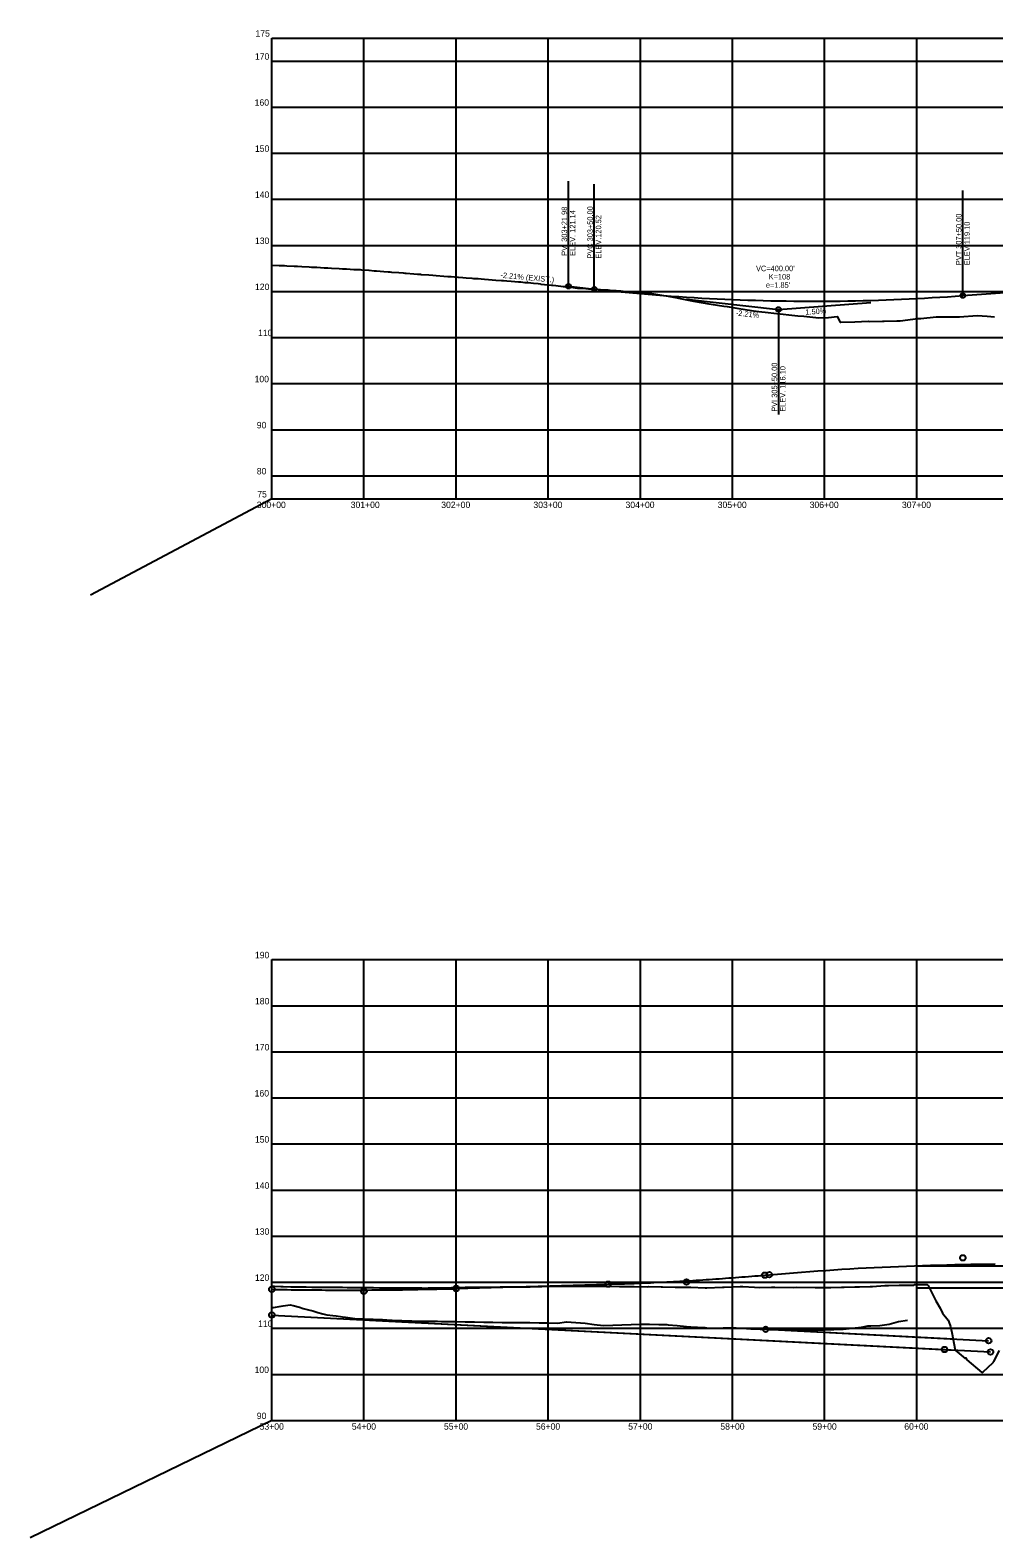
# Model space of a CAD drawing. Extents: x 1191541 to 1200065, y 1475807 to 1480451.
# Drawn here: x 1193644 to 1194690, y 1478815 to 1480451 of the extents above; entities that cross this region are included whole.
import ezdxf

# ---------------------------------------------------------------- set-up
doc = ezdxf.new("R2010")
doc.units = 0
for name, color, linetype in [('R_Exist Surface', 7, 'Continuous'), ('R_Grid', 7, 'Continuous'), ('R_No Plot', 7, 'Continuous'), ('R_Proposed Const Limits_Fill', 7, 'Continuous'), ('R_Proposed Const Limits_Hand', 7, 'Continuous'), ('R_Vert Alg', 7, 'Continuous'), ('R_Vert Alg Annot', 7, 'Continuous'), ('R_Water', 7, 'Continuous')]:
    doc.layers.add(name, color=color, linetype=linetype)

msp = doc.modelspace()

# ---------------------------------------------------------------- linework, layer by layer
at = {"layer": 'R_Exist Surface'}
msp.add_line((1193906.3, 1479942.5), (1193709.7, 1479838), dxfattribs=at)
for points in [[(1193906.3, 1480196.2), (1193906.5, 1480196.1), (1193914.4, 1480195.8), (1193918, 1480195.6), (1193920.1, 1480195.5), (1193922.5, 1480195.4), (1193930.7, 1480195), (1193931.8, 1480194.9), (1193934.2, 1480194.8), (1193938.8, 1480194.6), (1193946.9, 1480194.2), (1193949.4, 1480194), (1193951.7, 1480193.9), (1193955, 1480193.7), (1193963.1, 1480193.3), (1193967, 1480193.1), (1193971.2, 1480192.9), (1193979.3, 1480192.4), (1193983.2, 1480192.2), (1193984.5, 1480192.2), (1193987.4, 1480192), (1193995.5, 1480191.5), (1194001.7, 1480191.2), (1194002.1, 1480191.2), (1194003.6, 1480191.1), (1194011.7, 1480190.5), (1194011.8, 1480190.5), (1194017.5, 1480190), (1194017.7, 1480190), (1194019.9, 1480189.8), (1194028, 1480189.2), (1194032.5, 1480188.9), (1194033.4, 1480188.8), (1194034.3, 1480188.7), (1194036.1, 1480188.6), (1194044.2, 1480187.9), (1194049, 1480187.6), (1194050.8, 1480187.4), (1194052.3, 1480187.3), (1194060.4, 1480186.6), (1194064.6, 1480186.3), (1194067.7, 1480186.1), (1194068.5, 1480186), (1194076.6, 1480185.4), (1194080.9, 1480185.1), (1194084.7, 1480184.8), (1194092.9, 1480184.2), (1194092.9, 1480184.2), (1194097.2, 1480183.9), (1194101, 1480183.6), (1194108.3, 1480183), (1194109.1, 1480183), (1194113.6, 1480182.6), (1194117.2, 1480182.3), (1194123.5, 1480181.8), (1194125.3, 1480181.7), (1194130.1, 1480181.4), (1194133.4, 1480181.1), (1194137.2, 1480180.9), (1194141.5, 1480180.5), (1194149.4, 1480179.9), (1194149.6, 1480179.9), (1194155.7, 1480179.5), (1194157.7, 1480179.3), (1194161.2, 1480179.1), (1194165.9, 1480178.7), (1194174, 1480178), (1194176.7, 1480177.8), (1194181, 1480177.4), (1194182.1, 1480177.3), (1194184.7, 1480177.1), (1194190.2, 1480176.5), (1194195.3, 1480176), (1194197.9, 1480175.7), (1194198.3, 1480175.6), (1194206.4, 1480174.8), (1194209.8, 1480174.4), (1194211.4, 1480174.2), (1194214.5, 1480173.9), (1194222.6, 1480173), (1194224.7, 1480172.8), (1194225, 1480172.7), (1194228.3, 1480172.4), (1194230.7, 1480172.1), (1194237.9, 1480171.2), (1194238.8, 1480171.2), (1194239.6, 1480171.1), (1194247, 1480170.7), (1194250.1, 1480170.5), (1194253.2, 1480170.3), (1194255.1, 1480170.2), (1194261.9, 1480169.8), (1194263.2, 1480169.7), (1194266.7, 1480169.4), (1194271.3, 1480169.1), (1194273.5, 1480169), (1194279.4, 1480168.6), (1194280.1, 1480168.5), (1194285, 1480168.2), (1194287.5, 1480168), (1194293.6, 1480167.6), (1194295.6, 1480167.5), (1194297.2, 1480167.4), (1194303.7, 1480166.8), (1194311.6, 1480166.2), (1194312.4, 1480166.1), (1194316.6, 1480165.8), (1194325.1, 1480164.3), (1194329.6, 1480163.5), (1194336.4, 1480162.3), (1194346.1, 1480160.5), (1194347.6, 1480160.2), (1194347.8, 1480160.1), (1194364.1, 1480156.9), (1194366, 1480156.5), (1194380.7, 1480154.2), (1194383.2, 1480153.8), (1194397, 1480151.7), (1194400.4, 1480151.1), (1194413.2, 1480149.1), (1194417.7, 1480148.4), (1194429.2, 1480146.6), (1194434.9, 1480145.6), (1194445, 1480144.5), (1194451.2, 1480144), (1194461.1, 1480142.9), (1194467.5, 1480142.3), (1194477.2, 1480141.2), (1194483.7, 1480140.7), (1194493.3, 1480139.6), (1194500, 1480139), (1194510.4, 1480139.4), (1194519.8, 1480140.5), (1194523.3, 1480134.3), (1194523.9, 1480134.3), (1194539.2, 1480134.7), (1194553.5, 1480135.1), (1194555, 1480135), (1194569, 1480135.3), (1194570.8, 1480135.2), (1194584.6, 1480135.5), (1194586.4, 1480135.5), (1194588.2, 1480135.5), (1194607.5, 1480138), (1194610.6, 1480138), (1194627.5, 1480140), (1194631.6, 1480140.1), (1194649.8, 1480139.9), (1194651.5, 1480140.1), (1194652.5, 1480140.1), (1194671.9, 1480141.6), (1194682.6, 1480140.7), (1194686.5, 1480140.3), (1194690.8, 1480139.9)], [(1193906.3, 1479088.2), (1193908, 1479088.1), (1193909.4, 1479088.1), (1193916.2, 1479087.9), (1193918.8, 1479087.9), (1193926.8, 1479087.6), (1193929.5, 1479087.5), (1193933.7, 1479087.4), (1193940.2, 1479087.4), (1193943.6, 1479087.4), (1193949.9, 1479087.3), (1193951, 1479087.3), (1193959.7, 1479087.2), (1193961.7, 1479087.2), (1193966, 1479087.2), (1193972.4, 1479087.1), (1193976, 1479087.1), (1193982.1, 1479087), (1193983.1, 1479087), (1193988, 1479086.9), (1193993.9, 1479086.8), (1193998.2, 1479086.8), (1194004.6, 1479086.7), (1194004.8, 1479086.7), (1194015.3, 1479086.7), (1194016.8, 1479086.7), (1194023.2, 1479086.6), (1194026.1, 1479086.6), (1194035.3, 1479086.6), (1194036.8, 1479086.6), (1194041.3, 1479086.5), (1194047.5, 1479086.5), (1194053.9, 1479086.4), (1194058.2, 1479086.3), (1194059.3, 1479086.3), (1194069, 1479086.3), (1194072.5, 1479086.2), (1194076.1, 1479086.3), (1194079.7, 1479086.3), (1194087, 1479086.5), (1194090.4, 1479086.5), (1194090.5, 1479086.5), (1194101.2, 1479086.7), (1194101.6, 1479086.8), (1194104.7, 1479086.8), (1194116.2, 1479087), (1194118.9, 1479087), (1194130.8, 1479087.3), (1194134.1, 1479087.3), (1194151.9, 1479087.3), (1194154.3, 1479087.4), (1194172.9, 1479087.4), (1194174, 1479087.4), (1194185.7, 1479087.6), (1194186.7, 1479087.6), (1194198.5, 1479087.9), (1194199.5, 1479087.9), (1194211.3, 1479088.1), (1194223.2, 1479088.3), (1194224.1, 1479088.3), (1194238, 1479088.2), (1194239, 1479088.2), (1194252.9, 1479088.2), (1194253.8, 1479088.2), (1194254.8, 1479088.1), (1194268.7, 1479088.1), (1194269.5, 1479088.1), (1194283.5, 1479088), (1194284.3, 1479088), (1194298.6, 1479087.8), (1194299.7, 1479087.8), (1194313.7, 1479087.6), (1194315.1, 1479087.7), (1194328.9, 1479087.5), (1194330.5, 1479087.5), (1194344, 1479087.3), (1194359.2, 1479087), (1194361.1, 1479087), (1194376.6, 1479086.6), (1194378.3, 1479086.6), (1194395.4, 1479087.3), (1194397.1, 1479087.3), (1194414.7, 1479087.9), (1194415.7, 1479087.9), (1194417.6, 1479087.9), (1194430.3, 1479087.1), (1194435.6, 1479086.8), (1194448.7, 1479087.2), (1194452.3, 1479087.2), (1194472.7, 1479086.9), (1194475.3, 1479087), (1194496, 1479086.7), (1194498.5, 1479086.7), (1194500.8, 1479086.7), (1194513, 1479086.9), (1194524.7, 1479087.2), (1194527.6, 1479087.2), (1194539.1, 1479087.4), (1194541.7, 1479087.5), (1194544.2, 1479087.6), (1194555.8, 1479087.8), (1194558.4, 1479087.9), (1194571.7, 1479088.8), (1194572.3, 1479088.8), (1194575.5, 1479089.1), (1194587, 1479089.2), (1194588.6, 1479089.2), (1194602.5, 1479089.2), (1194603.1, 1479089.3), (1194604.2, 1479090.2), (1194617.5, 1479090.2), (1194618.6, 1479088.9), (1194625.2, 1479076), (1194627, 1479072.3), (1194631.5, 1479064.2), (1194634.2, 1479059), (1194640.2, 1479051.4), (1194640.9, 1479049.6), (1194643, 1479044.4), (1194644.2, 1479037.9), (1194647.8, 1479018.9), (1194658.8, 1479009.7), (1194659.7, 1479010.3), (1194660.5, 1479008.4), (1194676.8, 1478994.6), (1194678.4, 1478995.4), (1194688.7, 1479005.1), (1194689.5, 1479005.9), (1194689.6, 1479006), (1194689.9, 1479006.5), (1194696, 1479018.5)]]:
    msp.add_lwpolyline(points, dxfattribs=at)
at = {"layer": 'R_Grid'}
for p, q in [((1193906.3, 1480442.5), (1196406.3, 1480442.5)), ((1194006.3, 1479942.5), (1194006.3, 1480442.5)), ((1194106.3, 1479942.5), (1194106.3, 1480442.5)), ((1194206.3, 1479942.5), (1194206.3, 1480442.5)), ((1194306.3, 1479942.5), (1194306.3, 1480442.5)), ((1194406.3, 1479942.5), (1194406.3, 1480442.5)), ((1194506.3, 1479942.5), (1194506.3, 1480442.5)), ((1194606.3, 1479942.5), (1194606.3, 1480442.5)), ((1193906.3, 1480417.5), (1196406.3, 1480417.5)), ((1193906.3, 1480367.5), (1196406.3, 1480367.5)), ((1193906.3, 1480317.5), (1196406.3, 1480317.5)), ((1193906.3, 1480267.5), (1196406.3, 1480267.5)), ((1193906.3, 1480217.5), (1196406.3, 1480217.5)), ((1193906.3, 1480167.5), (1196406.3, 1480167.5)), ((1193906.3, 1480117.5), (1196406.3, 1480117.5)), ((1193906.3, 1480067.5), (1196406.3, 1480067.5)), ((1193906.3, 1480017.5), (1196406.3, 1480017.5)), ((1193906.3, 1479967.5), (1196406.3, 1479967.5)), ((1193906.3, 1479442.5), (1195406.3, 1479442.5)), ((1193906.3, 1479442.5), (1195406.3, 1479442.5)), ((1194006.3, 1478942.5), (1194006.3, 1479442.5)), ((1194106.3, 1478942.5), (1194106.3, 1479442.5)), ((1194206.3, 1478942.5), (1194206.3, 1479442.5)), ((1194306.3, 1478942.5), (1194306.3, 1479442.5)), ((1194406.3, 1478942.5), (1194406.3, 1479442.5)), ((1194506.3, 1478942.5), (1194506.3, 1479442.5)), ((1194606.3, 1478942.5), (1194606.3, 1479442.5)), ((1193906.3, 1479392.5), (1195406.3, 1479392.5)), ((1193906.3, 1479342.5), (1195406.3, 1479342.5)), ((1193906.3, 1479292.5), (1195406.3, 1479292.5)), ((1193906.3, 1479242.5), (1195406.3, 1479242.5)), ((1193906.3, 1479192.5), (1195406.3, 1479192.5)), ((1193906.3, 1479142.5), (1195406.3, 1479142.5)), ((1193906.3, 1479092.5), (1195406.3, 1479092.5)), ((1193906.3, 1479042.5), (1195406.3, 1479042.5)), ((1193906.3, 1478992.5), (1195406.3, 1478992.5))]:
    msp.add_line(p, q, dxfattribs=at)
at = {"layer": 'R_No Plot'}
for p, q in [((1194606.3, 1479110.3), (1194786.3, 1479110.3)), ((1194606.3, 1478942.5), (1194606.3, 1479110.3)), ((1194606.3, 1479086.5), (1194786.3, 1479086.5)), ((1193906.3, 1479056.9), (1194647.8, 1479018.9)), ((1194443.2, 1479041.4), (1194645.8, 1479031)), ((1193906.3, 1478942.5), (1193644, 1478815.2))]:
    msp.add_line(p, q, dxfattribs=at)
at = {"layer": 'R_Proposed Const Limits_Fill'}
msp.add_lwpolyline([(1193906.3, 1479065.2), (1193908, 1479065.1), (1193916.3, 1479066.5), (1193918.8, 1479067), (1193926.3, 1479067.9), (1193929.5, 1479067.3), (1193936.3, 1479065.3), (1193940.2, 1479064.1), (1193946.3, 1479062.7), (1193951, 1479061.3), (1193956.3, 1479059.7), (1193961.7, 1479058.1), (1193966.2, 1479057.3), (1193966.3, 1479057.3), (1193972.4, 1479056.5), (1193976.3, 1479055.9), (1193983.1, 1479055), (1193986.3, 1479054.5), (1193993.9, 1479053.5), (1193996.3, 1479053.3), (1194004.6, 1479052.9), (1194006.3, 1479052.8), (1194015.3, 1479052.4), (1194016.3, 1479052.4), (1194026.1, 1479051.9), (1194026.3, 1479051.9), (1194036.3, 1479051.4), (1194036.8, 1479051.4), (1194046.3, 1479051), (1194047.5, 1479051), (1194056.3, 1479050.6), (1194058.2, 1479050.6), (1194066.3, 1479050.4), (1194069, 1479050.4), (1194076.3, 1479050.2), (1194079.7, 1479050.2), (1194086.3, 1479050.1), (1194090.4, 1479050), (1194096.3, 1479049.9), (1194101.2, 1479049.9), (1194106.3, 1479049.8), (1194116.3, 1479049.6), (1194126.3, 1479049.5), (1194136.3, 1479049.3), (1194146.3, 1479049.2), (1194156.3, 1479048.9), (1194166.3, 1479048.7), (1194176.3, 1479048.7), (1194186.3, 1479048.7), (1194196.3, 1479048.6), (1194206.3, 1479048.6), (1194216.3, 1479048.2), (1194226.3, 1479049.6), (1194236.3, 1479048.8), (1194246.3, 1479048), (1194256.3, 1479046.6), (1194266.3, 1479045.6), (1194276.3, 1479046), (1194286.3, 1479046.4), (1194296.3, 1479046.8), (1194306.3, 1479047.1), (1194309.8, 1479047), (1194316.3, 1479046.9), (1194326.3, 1479046.7), (1194335.2, 1479046.5), (1194336.3, 1479046.4), (1194346.3, 1479045.4), (1194356.3, 1479044.4), (1194366.3, 1479043.9), (1194368.2, 1479043.7), (1194376.3, 1479043.3), (1194378.2, 1479043.1), (1194386.3, 1479042.8), (1194396.3, 1479043.1), (1194406.3, 1479043.3), (1194410.2, 1479043.1), (1194416.3, 1479042.6), (1194426.3, 1479041.9), (1194436.3, 1479041.6), (1194443.2, 1479041.4), (1194446.3, 1479041.3), (1194453.2, 1479041.3), (1194456.3, 1479041.4), (1194466.3, 1479041.2), (1194476.3, 1479040.9), (1194486.3, 1479040.7), (1194496.3, 1479040.7), (1194506.2, 1479040.9), (1194506.3, 1479040.9), (1194516.3, 1479041.2), (1194526.3, 1479041.6), (1194536.3, 1479042.7), (1194546.3, 1479043.7), (1194553.2, 1479045.1), (1194556.3, 1479045.2), (1194566.3, 1479045.7), (1194576.3, 1479047), (1194586.3, 1479049.9), (1194596.3, 1479051.4)], dxfattribs=at)
at = {"layer": 'R_Vert Alg'}
for p, q in [((1194656.3, 1480163), (1194997.1, 1480188.5)), ((1194228.3, 1480173.2), (1194256.3, 1480170.1)), ((1194356.3, 1480159.1), (1194456.3, 1480148)), ((1194456.3, 1480148), (1194556.3, 1480155.5)), ((1194106.3, 1479085.7), (1194271.3, 1479090.4)), ((1194441.3, 1479100.2), (1194446.3, 1479100.7)), ((1193906.3, 1479056.9), (1194686.3, 1479016.9)), ((1193906.3, 1479056.9), (1194636.3, 1479019.5)), ((1194442.3, 1479041.4), (1194684.3, 1479029))]:
    msp.add_line(p, q, dxfattribs=at)
for points in [[(1194256.3, 1480170.1), (1194264.7, 1480169.2), (1194273, 1480168.4), (1194281.3, 1480167.5), (1194289.7, 1480166.7), (1194298, 1480165.9), (1194306.3, 1480165.2), (1194314.7, 1480164.5), (1194323, 1480163.8), (1194331.3, 1480163.1), (1194339.7, 1480162.5), (1194348, 1480161.9), (1194356.3, 1480161.4), (1194364.7, 1480160.9), (1194373, 1480160.4), (1194381.3, 1480159.9), (1194389.7, 1480159.5), (1194398, 1480159.1), (1194406.3, 1480158.8), (1194414.7, 1480158.4), (1194423, 1480158.1), (1194431.3, 1480157.9), (1194439.7, 1480157.7), (1194448, 1480157.5), (1194464.7, 1480157.2), (1194473, 1480157.1), (1194481.3, 1480157), (1194489.7, 1480157), (1194498, 1480157), (1194506.3, 1480157), (1194514.7, 1480157), (1194523, 1480157.1), (1194531.3, 1480157.3), (1194539.7, 1480157.4), (1194548, 1480157.6), (1194556.3, 1480157.8), (1194564.7, 1480158.1), (1194573, 1480158.4), (1194581.3, 1480158.7), (1194589.7, 1480159), (1194598, 1480159.4), (1194606.3, 1480159.8), (1194614.7, 1480160.3), (1194623, 1480160.8), (1194631.3, 1480161.3), (1194639.7, 1480161.8), (1194648, 1480162.4), (1194656.3, 1480163)], [(1194446.3, 1479100.7), (1194455.1, 1479101.4), (1194463.8, 1479102.1), (1194472.6, 1479102.8), (1194481.3, 1479103.5), (1194490.1, 1479104.2), (1194498.8, 1479104.8), (1194507.6, 1479105.4), (1194516.3, 1479106), (1194525.1, 1479106.5), (1194533.8, 1479107.1), (1194542.6, 1479107.6), (1194551.3, 1479108), (1194560.1, 1479108.5), (1194568.8, 1479108.9), (1194577.6, 1479109.3), (1194586.3, 1479109.7), (1194595.1, 1479110), (1194603.8, 1479110.4), (1194612.6, 1479110.7), (1194621.3, 1479111), (1194630.1, 1479111.2), (1194638.8, 1479111.4), (1194647.6, 1479111.6), (1194665.1, 1479112), (1194673.8, 1479112.1), (1194682.6, 1479112.2), (1194691.3, 1479112.3)], [(1194271.3, 1479090.4), (1194274.9, 1479090.5), (1194278.4, 1479090.6), (1194281.9, 1479090.7), (1194285.5, 1479090.8), (1194289, 1479090.9), (1194292.6, 1479091), (1194296.1, 1479091.2), (1194299.7, 1479091.3), (1194303.2, 1479091.4), (1194306.7, 1479091.6), (1194310.3, 1479091.7), (1194313.8, 1479091.9), (1194317.4, 1479092), (1194320.9, 1479092.2), (1194324.4, 1479092.4), (1194328, 1479092.5), (1194331.5, 1479092.7), (1194335.1, 1479092.9), (1194338.6, 1479093.1), (1194342.2, 1479093.2), (1194345.7, 1479093.4), (1194349.2, 1479093.6), (1194352.8, 1479093.8), (1194359.9, 1479094.2), (1194363.4, 1479094.5), (1194366.9, 1479094.7), (1194370.5, 1479094.9), (1194374, 1479095.1), (1194377.6, 1479095.3), (1194381.1, 1479095.6), (1194384.7, 1479095.8), (1194388.2, 1479096.1), (1194391.7, 1479096.3), (1194395.3, 1479096.6), (1194398.8, 1479096.8), (1194402.4, 1479097.1), (1194405.9, 1479097.3), (1194409.4, 1479097.6), (1194413, 1479097.9), (1194416.5, 1479098.2), (1194420.1, 1479098.4), (1194423.6, 1479098.7), (1194427.2, 1479099), (1194430.7, 1479099.3), (1194434.2, 1479099.6), (1194437.8, 1479099.9), (1194441.3, 1479100.2)], [(1193906.3, 1479084.8), (1193910.5, 1479084.7), (1193914.7, 1479084.6), (1193918.8, 1479084.6), (1193923, 1479084.5), (1193927.2, 1479084.4), (1193931.3, 1479084.4), (1193935.5, 1479084.3), (1193939.7, 1479084.3), (1193943.8, 1479084.2), (1193948, 1479084.2), (1193952.2, 1479084.1), (1193956.3, 1479084.1), (1193960.5, 1479084.1), (1193964.7, 1479084), (1193968.8, 1479084), (1193973, 1479084), (1193977.2, 1479084), (1193981.3, 1479084), (1193985.5, 1479084), (1193989.7, 1479084), (1193993.8, 1479084), (1193998, 1479084), (1194002.2, 1479084), (1194010.5, 1479084), (1194014.7, 1479084.1), (1194018.8, 1479084.1), (1194023, 1479084.1), (1194027.2, 1479084.2), (1194031.3, 1479084.2), (1194035.5, 1479084.2), (1194039.7, 1479084.3), (1194043.8, 1479084.3), (1194048, 1479084.4), (1194052.2, 1479084.5), (1194056.3, 1479084.5), (1194060.5, 1479084.6), (1194064.7, 1479084.7), (1194068.8, 1479084.8), (1194073, 1479084.8), (1194077.2, 1479084.9), (1194081.3, 1479085), (1194085.5, 1479085.1), (1194089.7, 1479085.2), (1194093.8, 1479085.3), (1194098, 1479085.4), (1194102.2, 1479085.5), (1194106.3, 1479085.7)]]:
    msp.add_lwpolyline(points, dxfattribs=at)
at = {"layer": 'R_Vert Alg Annot'}
for p, q in [((1194228.3, 1480203.2), (1194228.3, 1480287.2)), ((1194256.3, 1480200.1), (1194256.3, 1480284.1)), ((1194656.3, 1480193), (1194656.3, 1480277)), ((1194228.3, 1480173.2), (1194228.3, 1480203.2)), ((1194256.3, 1480170.1), (1194256.3, 1480200.1)), ((1194656.3, 1480163), (1194656.3, 1480193)), ((1194456.3, 1480148), (1194456.3, 1480118)), ((1194456.3, 1480118), (1194456.3, 1480034))]:
    msp.add_line(p, q, dxfattribs=at)
for centre, radius in [((1194228.3, 1480173.2), 2.5), ((1194256.3, 1480170.1), 2.5), ((1194656.3, 1480163), 2.5), ((1194456.3, 1480148), 2.5), ((1194656.3, 1479119), 3), ((1194441.3, 1479100.2), 3), ((1194446.3, 1479100.7), 3), ((1193906.3, 1479084.8), 3), ((1194106.3, 1479085.7), 3), ((1194271.3, 1479090.4), 3), ((1194356.3, 1479092.8), 3), ((1194006.3, 1479082.8), 3), ((1193906.3, 1479056.9), 3), ((1193906.3, 1479056.9), 3), ((1194442.3, 1479041.4), 3), ((1194636.3, 1479019.5), 3), ((1194684.3, 1479029), 3), ((1194686.3, 1479016.9), 3)]:
    msp.add_circle(centre, radius, dxfattribs=at)
at = {"layer": 'R_Water'}
for p, q in [((1193906.3, 1479942.5), (1193906.3, 1480442.5)), ((1193906.3, 1479942.5), (1196406.3, 1479942.5)), ((1193906.3, 1478942.5), (1193906.3, 1479442.5)), ((1193906.3, 1478942.5), (1195406.3, 1478942.5))]:
    msp.add_line(p, q, dxfattribs=at)

# ---------------------------------------------------------------- texts
at = {"layer": 'R_Proposed Const Limits_Hand'}
for s, height, p in [('175', 7, (1193888.6, 1480444)), ('170', 7, (1193888, 1480419)), ('160', 7, (1193887.7, 1480369)), ('150', 7, (1193888, 1480319)), ('140', 7, (1193888, 1480269)), ('130', 7, (1193888, 1480219)), ('120', 7, (1193888, 1480169)), ('110', 7, (1193891.4, 1480119)), ('100', 7, (1193887.6, 1480069)), ('90', 7, (1193890, 1480019)), ('80', 7, (1193890, 1479969)), ('300+00', 7, (1193890, 1479932.5)), ('75', 7, (1193890.5, 1479944)), ('-', 0.0001, (1193906.3, 1479942.5)), ('301+00', 7, (1193991.9, 1479932.5)), ('302+00', 7, (1194090.2, 1479932.5)), ('303+00', 7, (1194190.2, 1479932.5)), ('304+00', 7, (1194290.2, 1479932.5)), ('305+00', 7, (1194390.2, 1479932.5)), ('306+00', 7, (1194490, 1479932.5)), ('307+00', 7, (1194590.2, 1479932.5)), ('190', 7, (1193888, 1479444)), ('190', 7, (1193888, 1479444)), ('180', 7, (1193888, 1479394)), ('170', 7, (1193888, 1479344)), ('160', 7, (1193887.7, 1479294)), ('150', 7, (1193888, 1479244)), ('140', 7, (1193888, 1479194)), ('130', 7, (1193888, 1479144)), ('120', 7, (1193888, 1479094)), ('110', 7, (1193891.4, 1479044)), ('100', 7, (1193887.6, 1478994)), ('90', 7, (1193890, 1478944)), ('53+00', 7, (1193893.1, 1478932.5)), ('-', 0.0001, (1193906.3, 1478942.5)), ('54+00', 7, (1193993.1, 1478932.5)), ('55+00', 7, (1194093.1, 1478932.5)), ('56+00', 7, (1194193, 1478932.5)), ('57+00', 7, (1194293.1, 1478932.5)), ('58+00', 7, (1194393.1, 1478932.5)), ('59+00', 7, (1194493.1, 1478932.5)), ('60+00', 7, (1194592.7, 1478932.5))]:
    msp.add_text(s, height=height, dxfattribs=at).set_placement(p)
at = {"layer": 'R_Vert Alg Annot'}
for s, rotation, p in [('PVI 303+21.98', 90, (1194226.8, 1480206.2)), ('ELEV. 121.14', 90, (1194235.8, 1480206.2)), ('PVC 303+50.00', 90, (1194254.8, 1480203.1)), ('ELEV.120.52', 90, (1194263.8, 1480203.1)), ('PVT 307+50.00', 90, (1194654.8, 1480196)), ('ELEV.119.10', 90, (1194663.8, 1480196)), ('-2.21% (EXIST.)', 354.847, (1194154.3, 1480182.4)), ('1.50%', 4.2823, (1194485.6, 1480142)), ('-2.21%', 353.6935, (1194409.7, 1480141.4)), ('PVI 305+50.00', 90, (1194454.8, 1480037)), ('ELEV. 116.10', 90, (1194463.8, 1480037))]:
    msp.add_text(s, height=6, rotation=rotation, dxfattribs=at).set_placement(p)
for s, p in [("VC=400.00'", (1194431.8, 1480189.5)), ('K=108', (1194445.6, 1480180.5)), ("e=1.85'", (1194442.5, 1480171.5))]:
    msp.add_text(s, height=6, dxfattribs=at).set_placement(p)

doc.saveas('drawing.dxf')
